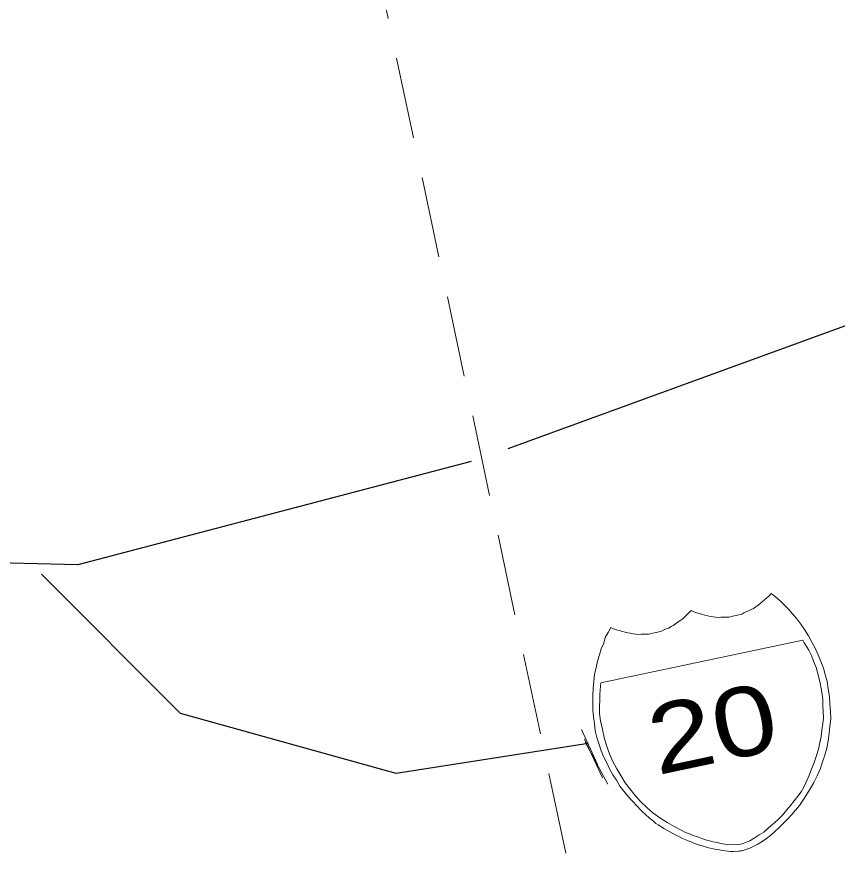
# Model space of a CAD drawing. Extents: x 2357218 to 2371708, y 6973728 to 6980157.
# Drawn here: x 2371276.8 to 2371337.4, y 6977543.5 to 6977607.1 of the extents above; entities that cross this region are included whole.
import ezdxf

# ---------------------------------------------------------------- set-up
doc = ezdxf.new("R2010")
doc.units = 0
doc.header["$LTSCALE"] = 2
doc.linetypes.add('MEDIUM_DASHED', pattern=[4.5, 3, -1.5])
doc.layers.add('62', color=7, linetype='Continuous', lineweight=13)
doc.layers.add('63', color=7, linetype='Continuous', lineweight=13)

msp = doc.modelspace()

# ---------------------------------------------------------------- linework, layer by layer
at = {"layer": '62', "linetype": 'MEDIUM_DASHED'}
msp.add_line((2371295.479, 6977648.054), (2371334.113, 6977466.412), dxfattribs=at)
at = {"layer": '62'}
for p, q in [((2371318.496, 6977554.485), (2371319.666, 6977551.906)), ((2371318.717, 6977553.774), (2371320.038, 6977550.904)), ((2371318.766, 6977553.533), (2371320.436, 6977550.437))]:
    msp.add_line(p, q, dxfattribs=at)
at = {"layer": '62', "lineweight": 25}
for points in [[(2371364.474, 6977587.426), (2371358.059, 6977585.67), (2371349.551, 6977586.738), (2371337.909, 6977584.264), (2371313.055, 6977575.208)], [(2371310.336, 6977574.263), (2371281.29, 6977566.64), (2371261.473, 6977567.121), (2371246.731, 6977571.21), (2371231.154, 6977571.117), (2371224.489, 6977568.161)], [(2371318.97, 6977553.437), (2371304.81, 6977551.232), (2371288.893, 6977555.651), (2371278.629, 6977565.959)]]:
    msp.add_lwpolyline(points, dxfattribs=at)
at = {"layer": '62'}
for points in [[(2371327.413, 6977562.962), (2371327.607, 6977562.912), (2371327.824, 6977562.866), (2371327.992, 6977562.833), (2371328.21, 6977562.787), (2371328.417, 6977562.785), (2371328.608, 6977562.755), (2371328.788, 6977562.772), (2371328.993, 6977562.77), (2371329.181, 6977562.762), (2371329.381, 6977562.782), (2371329.559, 6977562.82), (2371329.758, 6977562.864), (2371329.934, 6977562.901), (2371330.11, 6977562.939), (2371330.327, 6977563.007), (2371330.47, 6977563.083), (2371330.637, 6977563.165), (2371330.832, 6977563.229), (2371331.015, 6977563.338), (2371331.184, 6977563.419), (2371331.361, 6977563.548), (2371331.523, 6977563.651), (2371331.679, 6977563.776), (2371331.84, 6977563.903), (2371331.99, 6977564.052), (2371332.164, 6977564.203), (2371332.34, 6977564.357), (2371332.488, 6977564.526), (2371332.818, 6977564.275), (2371333.124, 6977564.015), (2371333.446, 6977563.693), (2371333.768, 6977563.371), (2371334.072, 6977563.018), (2371334.382, 6977562.649), (2371334.673, 6977562.25), (2371334.964, 6977561.852), (2371335.248, 6977561.383), (2371335.503, 6977560.932), (2371335.742, 6977560.475), (2371335.959, 6977559.993), (2371336.154, 6977559.504), (2371336.35, 6977559.018), (2371336.474, 6977558.539), (2371336.632, 6977558.02), (2371336.699, 6977557.481), (2371336.799, 6977556.906), (2371336.824, 6977556.357), (2371336.869, 6977555.816), (2371336.895, 6977555.27), (2371336.829, 6977554.704), (2371336.778, 6977554.187), (2371336.709, 6977553.644), (2371336.593, 6977553.111), (2371336.453, 6977552.577), (2371336.285, 6977552.081), (2371336.117, 6977551.561), (2371335.882, 6977551.051), (2371335.64, 6977550.564), (2371335.372, 6977550.092), (2371335.064, 6977549.59), (2371334.839, 6977549.243), (2371334.595, 6977548.87), (2371334.299, 6977548.531), (2371334.027, 6977548.197), (2371333.707, 6977547.853), (2371333.383, 6977547.531), (2371333.08, 6977547.235), (2371332.773, 6977546.939), (2371332.458, 6977546.69), (2371332.143, 6977546.439), (2371331.824, 6977546.209), (2371331.502, 6977546.004), (2371331.207, 6977545.872), (2371330.917, 6977545.716), (2371330.619, 6977545.609), (2371330.361, 6977545.531)], [(2371330.361, 6977545.531), (2371330.177, 6977545.514), (2371330.024, 6977545.481), (2371329.838, 6977545.489), (2371329.681, 6977545.478), (2371329.494, 6977545.485), (2371329.308, 6977545.491), (2371329.075, 6977545.511), (2371328.864, 6977545.535), (2371328.669, 6977545.584), (2371328.451, 6977545.629), (2371328.213, 6977545.673), (2371327.996, 6977545.719), (2371327.757, 6977545.76), (2371327.56, 6977545.831), (2371327.31, 6977545.917), (2371327.066, 6977545.981), (2371326.84, 6977546.07), (2371326.586, 6977546.178), (2371326.363, 6977546.267), (2371326.137, 6977546.356), (2371325.905, 6977546.468), (2371325.674, 6977546.582), (2371325.442, 6977546.692), (2371325.234, 6977546.808), (2371325.003, 6977546.923), (2371324.794, 6977547.039), (2371324.58, 6977547.178), (2371324.393, 6977547.298), (2371324.158, 6977547.432), (2371323.971, 6977547.552), (2371323.802, 6977547.702), (2371323.606, 6977547.867), (2371323.265, 6977548.163), (2371322.897, 6977548.499), (2371322.57, 6977548.842), (2371322.244, 6977549.187), (2371321.914, 6977549.554), (2371321.604, 6977549.925), (2371321.317, 6977550.302), (2371321.065, 6977550.731), (2371320.795, 6977551.134), (2371320.564, 6977551.567), (2371320.356, 6977552.008), (2371320.148, 6977552.446), (2371319.936, 6977552.907), (2371319.788, 6977553.38), (2371319.631, 6977553.9), (2371319.508, 6977554.379), (2371319.439, 6977554.919), (2371319.381, 6977555.411), (2371319.338, 6977555.932), (2371319.32, 6977556.457), (2371319.321, 6977556.984), (2371319.348, 6977557.498), (2371319.4, 6977558.014), (2371319.449, 6977558.554), (2371319.575, 6977559.039), (2371319.68, 6977559.524), (2371319.811, 6977559.987), (2371319.945, 6977560.433), (2371320.128, 6977560.862), (2371320.248, 6977561.279), (2371320.447, 6977561.643), (2371320.645, 6977562.008), (2371320.849, 6977561.915), (2371321.072, 6977561.846), (2371321.293, 6977561.778), (2371321.495, 6977561.704), (2371321.709, 6977561.658), (2371321.904, 6977561.607), (2371322.116, 6977561.583), (2371322.312, 6977561.534), (2371322.496, 6977561.527), (2371322.686, 6977561.498), (2371322.89, 6977561.518), (2371323.076, 6977561.511), (2371323.306, 6977561.515), (2371323.463, 6977561.526), (2371323.639, 6977561.563), (2371323.86, 6977561.608), (2371324.036, 6977561.648), (2371324.211, 6977561.683), (2371324.406, 6977561.747), (2371324.572, 6977561.829), (2371324.737, 6977561.909), (2371324.91, 6977561.97), (2371325.117, 6977562.082), (2371325.284, 6977562.164), (2371325.439, 6977562.29), (2371325.601, 6977562.392), (2371325.78, 6977562.523), (2371325.961, 6977562.654), (2371326.113, 6977562.803), (2371326.266, 6977562.951), (2371326.419, 6977563.097), (2371326.588, 6977563.272), (2371326.793, 6977563.176), (2371326.992, 6977563.104), (2371327.213, 6977563.035), (2371327.413, 6977562.962)]]:
    msp.add_lwpolyline(points, dxfattribs=at)
msp.add_lwpolyline([(2371334.829, 6977561.085), (2371319.928, 6977557.918), (2371319.886, 6977557.68), (2371319.859, 6977557.376), (2371319.837, 6977557.048), (2371319.835, 6977556.634), (2371319.817, 6977556.17), (2371319.831, 6977555.669), (2371319.905, 6977555.108), (2371320.035, 6977554.491), (2371320.161, 6977553.897), (2371320.336, 6977553.292), (2371320.554, 6977552.694), (2371320.815, 6977552.128), (2371321.094, 6977551.566), (2371321.382, 6977551.074), (2371321.703, 6977550.546), (2371322.08, 6977550.072), (2371322.454, 6977549.601), (2371322.849, 6977549.156), (2371323.309, 6977548.723), (2371323.76, 6977548.335), (2371324.274, 6977547.964), (2371324.808, 6977547.618), (2371325.333, 6977547.313), (2371325.902, 6977547.02), (2371326.163, 6977546.869), (2371326.46, 6977546.772), (2371326.74, 6977546.646), (2371327.059, 6977546.552), (2371327.334, 6977546.451), (2371327.635, 6977546.33), (2371327.929, 6977546.257), (2371328.22, 6977546.179), (2371328.507, 6977546.126), (2371328.773, 6977546.068), (2371329.063, 6977546.013), (2371329.298, 6977545.972), (2371329.572, 6977545.984), (2371329.805, 6977545.963), (2371330.031, 6977545.988), (2371330.258, 6977546.016), (2371330.554, 6977546.123), (2371330.916, 6977546.27), (2371331.245, 6977546.453), (2371331.607, 6977546.691), (2371331.953, 6977546.903), (2371332.301, 6977547.208), (2371332.63, 6977547.508), (2371332.98, 6977547.811), (2371333.321, 6977548.161), (2371333.636, 6977548.527), (2371333.93, 6977548.864), (2371334.2, 6977549.222), (2371334.474, 6977549.557), (2371334.704, 6977549.88), (2371334.907, 6977550.224), (2371335.031, 6977550.503), (2371335.285, 6977551.041), (2371335.477, 6977551.542), (2371335.67, 6977552.04), (2371335.836, 6977552.558), (2371335.991, 6977553.029), (2371336.095, 6977553.513), (2371336.18, 6977553.967), (2371336.243, 6977554.44), (2371336.302, 6977554.913), (2371336.349, 6977555.336), (2371336.344, 6977555.797), (2371336.321, 6977556.229), (2371336.299, 6977556.661), (2371336.253, 6977557.088), (2371336.188, 6977557.51), (2371336.103, 6977557.908), (2371335.973, 6977558.523), (2371335.81, 6977559.065), (2371335.62, 6977559.529), (2371335.46, 6977559.955), (2371335.266, 6977560.328), (2371335.091, 6977560.612), (2371334.942, 6977560.881)], close=True, dxfattribs=at)
at = {"layer": '63', "linetype": 'MEDIUM_DASHED'}
msp.add_line((2371295.479, 6977648.054), (2371334.113, 6977466.412), dxfattribs=at)
at = {"layer": '63'}
for p, q in [((2371318.496, 6977554.485), (2371319.666, 6977551.906)), ((2371318.717, 6977553.774), (2371320.038, 6977550.904)), ((2371318.766, 6977553.533), (2371320.436, 6977550.437))]:
    msp.add_line(p, q, dxfattribs=at)
at = {"layer": '63', "lineweight": 25}
for points in [[(2371364.474, 6977587.426), (2371358.059, 6977585.67), (2371349.551, 6977586.738), (2371337.909, 6977584.264), (2371313.055, 6977575.208)], [(2371310.336, 6977574.263), (2371281.29, 6977566.64), (2371261.473, 6977567.121), (2371246.731, 6977571.21), (2371231.154, 6977571.117), (2371224.489, 6977568.161)], [(2371318.97, 6977553.437), (2371304.81, 6977551.232), (2371288.893, 6977555.651), (2371278.629, 6977565.959)]]:
    msp.add_lwpolyline(points, dxfattribs=at)
at = {"layer": '63'}
for points in [[(2371327.413, 6977562.962), (2371327.607, 6977562.912), (2371327.824, 6977562.866), (2371327.992, 6977562.833), (2371328.21, 6977562.787), (2371328.417, 6977562.785), (2371328.608, 6977562.755), (2371328.788, 6977562.772), (2371328.993, 6977562.77), (2371329.181, 6977562.762), (2371329.381, 6977562.782), (2371329.559, 6977562.82), (2371329.758, 6977562.864), (2371329.934, 6977562.901), (2371330.11, 6977562.939), (2371330.327, 6977563.007), (2371330.47, 6977563.083), (2371330.637, 6977563.165), (2371330.832, 6977563.229), (2371331.015, 6977563.338), (2371331.184, 6977563.419), (2371331.361, 6977563.548), (2371331.523, 6977563.651), (2371331.679, 6977563.776), (2371331.84, 6977563.903), (2371331.99, 6977564.052), (2371332.164, 6977564.203), (2371332.34, 6977564.357), (2371332.488, 6977564.526), (2371332.818, 6977564.275), (2371333.124, 6977564.015), (2371333.446, 6977563.693), (2371333.768, 6977563.371), (2371334.072, 6977563.018), (2371334.382, 6977562.649), (2371334.673, 6977562.25), (2371334.964, 6977561.852), (2371335.248, 6977561.383), (2371335.503, 6977560.932), (2371335.742, 6977560.475), (2371335.959, 6977559.993), (2371336.154, 6977559.504), (2371336.35, 6977559.018), (2371336.474, 6977558.539), (2371336.632, 6977558.02), (2371336.699, 6977557.481), (2371336.799, 6977556.906), (2371336.824, 6977556.357), (2371336.869, 6977555.816), (2371336.895, 6977555.27), (2371336.829, 6977554.704), (2371336.778, 6977554.187), (2371336.709, 6977553.644), (2371336.593, 6977553.111), (2371336.453, 6977552.577), (2371336.285, 6977552.081), (2371336.117, 6977551.561), (2371335.882, 6977551.051), (2371335.64, 6977550.564), (2371335.372, 6977550.092), (2371335.064, 6977549.59), (2371334.839, 6977549.243), (2371334.595, 6977548.87), (2371334.299, 6977548.531), (2371334.027, 6977548.197), (2371333.707, 6977547.853), (2371333.383, 6977547.531), (2371333.08, 6977547.235), (2371332.773, 6977546.939), (2371332.458, 6977546.69), (2371332.143, 6977546.439), (2371331.824, 6977546.209), (2371331.502, 6977546.004), (2371331.207, 6977545.872), (2371330.917, 6977545.716), (2371330.619, 6977545.609), (2371330.361, 6977545.531)], [(2371330.361, 6977545.531), (2371330.177, 6977545.514), (2371330.024, 6977545.481), (2371329.838, 6977545.489), (2371329.681, 6977545.478), (2371329.494, 6977545.485), (2371329.308, 6977545.491), (2371329.075, 6977545.511), (2371328.864, 6977545.535), (2371328.669, 6977545.584), (2371328.451, 6977545.629), (2371328.213, 6977545.673), (2371327.996, 6977545.719), (2371327.757, 6977545.76), (2371327.56, 6977545.831), (2371327.31, 6977545.917), (2371327.066, 6977545.981), (2371326.84, 6977546.07), (2371326.586, 6977546.178), (2371326.363, 6977546.267), (2371326.137, 6977546.356), (2371325.905, 6977546.468), (2371325.674, 6977546.582), (2371325.442, 6977546.692), (2371325.234, 6977546.808), (2371325.003, 6977546.923), (2371324.794, 6977547.039), (2371324.58, 6977547.178), (2371324.393, 6977547.298), (2371324.158, 6977547.432), (2371323.971, 6977547.552), (2371323.802, 6977547.702), (2371323.606, 6977547.867), (2371323.265, 6977548.163), (2371322.897, 6977548.499), (2371322.57, 6977548.842), (2371322.244, 6977549.187), (2371321.914, 6977549.554), (2371321.604, 6977549.925), (2371321.317, 6977550.302), (2371321.065, 6977550.731), (2371320.795, 6977551.134), (2371320.564, 6977551.567), (2371320.356, 6977552.008), (2371320.148, 6977552.446), (2371319.936, 6977552.907), (2371319.788, 6977553.38), (2371319.631, 6977553.9), (2371319.508, 6977554.379), (2371319.439, 6977554.919), (2371319.381, 6977555.411), (2371319.338, 6977555.932), (2371319.32, 6977556.457), (2371319.321, 6977556.984), (2371319.348, 6977557.498), (2371319.4, 6977558.014), (2371319.449, 6977558.554), (2371319.575, 6977559.039), (2371319.68, 6977559.524), (2371319.811, 6977559.987), (2371319.945, 6977560.433), (2371320.128, 6977560.862), (2371320.248, 6977561.279), (2371320.447, 6977561.643), (2371320.645, 6977562.008), (2371320.849, 6977561.915), (2371321.072, 6977561.846), (2371321.293, 6977561.778), (2371321.495, 6977561.704), (2371321.709, 6977561.658), (2371321.904, 6977561.607), (2371322.116, 6977561.583), (2371322.312, 6977561.534), (2371322.496, 6977561.527), (2371322.686, 6977561.498), (2371322.89, 6977561.518), (2371323.076, 6977561.511), (2371323.306, 6977561.515), (2371323.463, 6977561.526), (2371323.639, 6977561.563), (2371323.86, 6977561.608), (2371324.036, 6977561.648), (2371324.211, 6977561.683), (2371324.406, 6977561.747), (2371324.572, 6977561.829), (2371324.737, 6977561.909), (2371324.91, 6977561.97), (2371325.117, 6977562.082), (2371325.284, 6977562.164), (2371325.439, 6977562.29), (2371325.601, 6977562.392), (2371325.78, 6977562.523), (2371325.961, 6977562.654), (2371326.113, 6977562.803), (2371326.266, 6977562.951), (2371326.419, 6977563.097), (2371326.588, 6977563.272), (2371326.793, 6977563.176), (2371326.992, 6977563.104), (2371327.213, 6977563.035), (2371327.413, 6977562.962)]]:
    msp.add_lwpolyline(points, dxfattribs=at)
msp.add_lwpolyline([(2371334.829, 6977561.085), (2371319.928, 6977557.918), (2371319.886, 6977557.68), (2371319.859, 6977557.376), (2371319.837, 6977557.048), (2371319.835, 6977556.634), (2371319.817, 6977556.17), (2371319.831, 6977555.669), (2371319.905, 6977555.108), (2371320.035, 6977554.491), (2371320.161, 6977553.897), (2371320.336, 6977553.292), (2371320.554, 6977552.694), (2371320.815, 6977552.128), (2371321.094, 6977551.566), (2371321.382, 6977551.074), (2371321.703, 6977550.546), (2371322.08, 6977550.072), (2371322.454, 6977549.601), (2371322.849, 6977549.156), (2371323.309, 6977548.723), (2371323.76, 6977548.335), (2371324.274, 6977547.964), (2371324.808, 6977547.618), (2371325.333, 6977547.313), (2371325.902, 6977547.02), (2371326.163, 6977546.869), (2371326.46, 6977546.772), (2371326.74, 6977546.646), (2371327.059, 6977546.552), (2371327.334, 6977546.451), (2371327.635, 6977546.33), (2371327.929, 6977546.257), (2371328.22, 6977546.179), (2371328.507, 6977546.126), (2371328.773, 6977546.068), (2371329.063, 6977546.013), (2371329.298, 6977545.972), (2371329.572, 6977545.984), (2371329.805, 6977545.963), (2371330.031, 6977545.988), (2371330.258, 6977546.016), (2371330.554, 6977546.123), (2371330.916, 6977546.27), (2371331.245, 6977546.453), (2371331.607, 6977546.691), (2371331.953, 6977546.903), (2371332.301, 6977547.208), (2371332.63, 6977547.508), (2371332.98, 6977547.811), (2371333.321, 6977548.161), (2371333.636, 6977548.527), (2371333.93, 6977548.864), (2371334.2, 6977549.222), (2371334.474, 6977549.557), (2371334.704, 6977549.88), (2371334.907, 6977550.224), (2371335.031, 6977550.503), (2371335.285, 6977551.041), (2371335.477, 6977551.542), (2371335.67, 6977552.04), (2371335.836, 6977552.558), (2371335.991, 6977553.029), (2371336.095, 6977553.513), (2371336.18, 6977553.967), (2371336.243, 6977554.44), (2371336.302, 6977554.913), (2371336.349, 6977555.336), (2371336.344, 6977555.797), (2371336.321, 6977556.229), (2371336.299, 6977556.661), (2371336.253, 6977557.088), (2371336.188, 6977557.51), (2371336.103, 6977557.908), (2371335.973, 6977558.523), (2371335.81, 6977559.065), (2371335.62, 6977559.529), (2371335.46, 6977559.955), (2371335.266, 6977560.328), (2371335.091, 6977560.612), (2371334.942, 6977560.881)], close=True, dxfattribs=at)

# ---------------------------------------------------------------- texts
at = {"layer": '62', "width": 1.25}
msp.add_text('20', height=5.099, rotation=12, dxfattribs=at).set_placement((2371324.069, 6977551.095))
at = {"layer": '63', "width": 1.25}
msp.add_text('20', height=5.099, rotation=12, dxfattribs=at).set_placement((2371324.069, 6977551.095))

doc.saveas('drawing.dxf')
